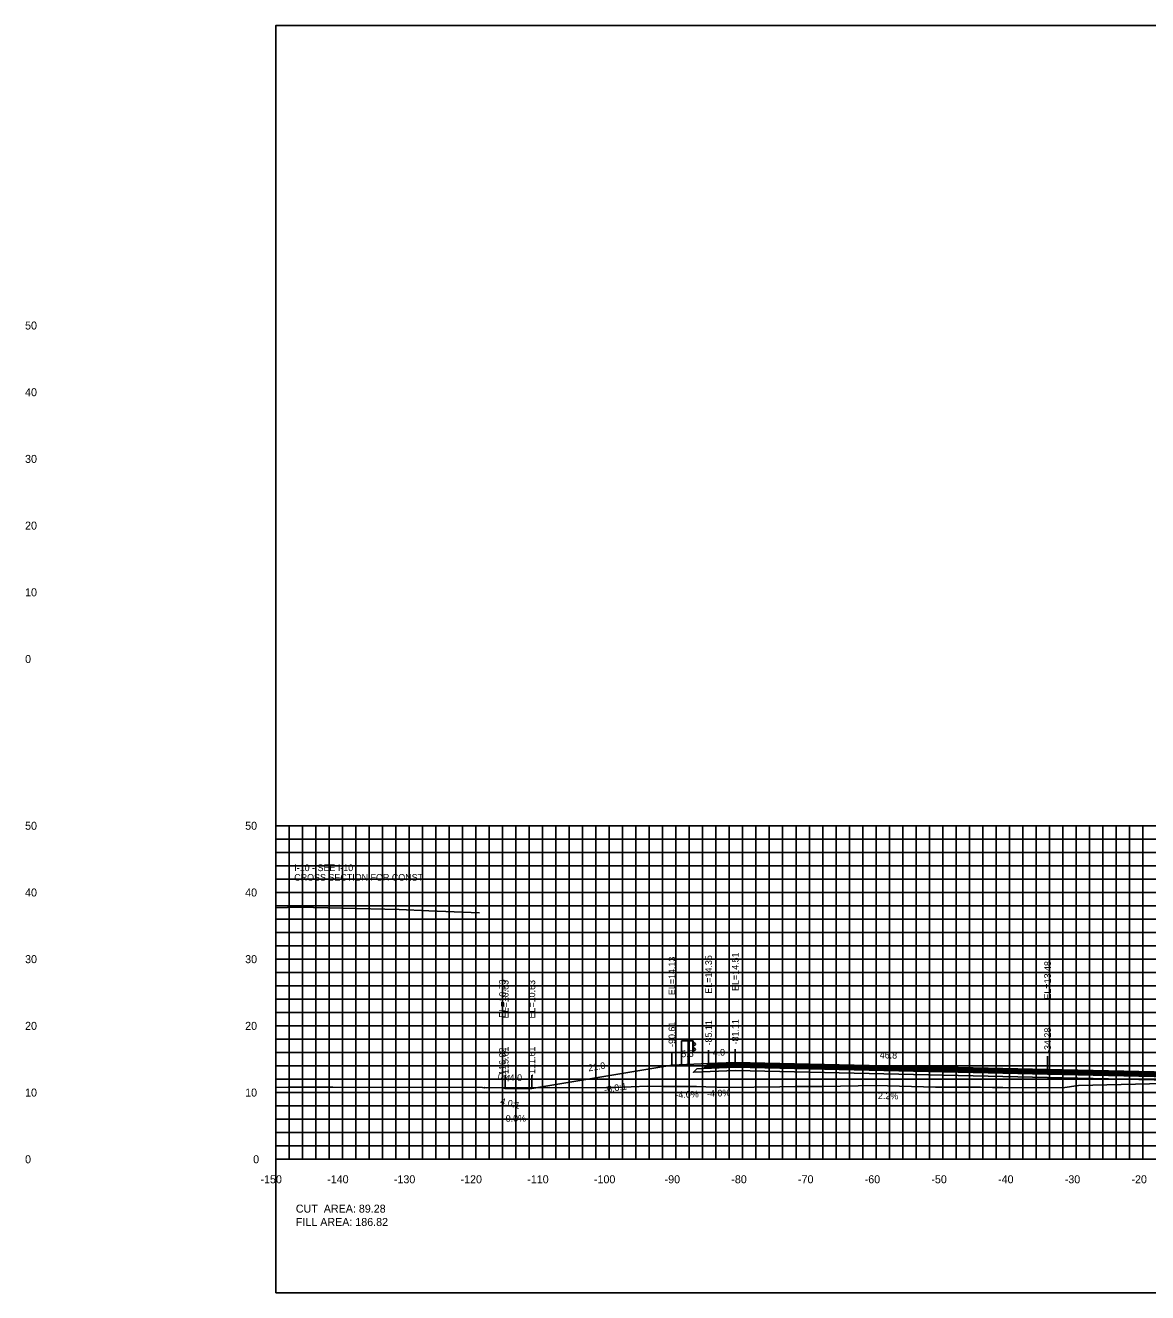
# Model space of a CAD drawing. Extents: x 1800976 to 1805104, y 250057 to 250580.
# Drawn here: x 1804483.4 to 1804651.7, y 250079.4 to 250269.4 of the extents above; entities that cross this region are included whole.
import ezdxf

# ---------------------------------------------------------------- set-up
doc = ezdxf.new("R2010")
doc.units = 0
for name, color, linetype in [('10', 7, 'Continuous'), ('3', 7, 'Continuous'), ('31', 7, 'Continuous'), ('4', 7, 'Continuous'), ('60', 7, 'Continuous'), ('ANNO-TXT', 7, 'Continuous'), ('BASE', 7, 'Continuous'), ('CL-CNST', 7, 'Continuous'), ('Level 1', 7, 'Continuous'), ('Level 62', 7, 'Continuous'), ('LOWER BINDER', 7, 'Continuous'), ('M-ROADS', 7, 'Continuous'), ('UPPER BINDER', 7, 'Continuous'), ('WEARING', 7, 'Continuous')]:
    doc.layers.add(name, color=color, linetype=linetype)

msp = doc.modelspace()

# ---------------------------------------------------------------- linework, layer by layer
for p, q in [((1804580.39, 250113.56), (1804580.39, 250115.56)), ((1804585.89, 250113.78), (1804585.89, 250115.78)), ((1804589.89, 250113.94), (1804589.89, 250115.94)), ((1804636.72, 250112.91), (1804636.72, 250114.91)), ((1804554.98, 250110.17), (1804554.98, 250112.17)), ((1804555.39, 250110.06), (1804555.39, 250112.06)), ((1804559.39, 250110.06), (1804559.39, 250112.06))]:
    msp.add_line(p, q)
msp.add_lwpolyline([(1804521, 250079.43), (1804821, 250079.43), (1804821, 250269.43), (1804521, 250269.43)], close=True)
at = {"layer": '60'}
for p, q in [((1804520.94, 250149.43), (1804521, 250149.43)), ((1804521, 250099.43), (1804521, 250149.43)), ((1804520.94, 250139.43), (1804521, 250139.43)), ((1804520.94, 250129.43), (1804521, 250129.43)), ((1804520.94, 250119.43), (1804521, 250119.43)), ((1804520.94, 250109.43), (1804521, 250109.43)), ((1804520.94, 250099.43), (1804521, 250099.43)), ((1804521, 250099.43), (1804821, 250099.43)), ((1804521, 250099.37), (1804521, 250099.43)), ((1804531, 250099.37), (1804531, 250099.43)), ((1804541, 250099.37), (1804541, 250099.43)), ((1804551, 250099.37), (1804551, 250099.43)), ((1804561, 250099.37), (1804561, 250099.43)), ((1804571, 250099.37), (1804571, 250099.43)), ((1804581, 250099.37), (1804581, 250099.43)), ((1804591, 250099.37), (1804591, 250099.43)), ((1804601, 250099.37), (1804601, 250099.43)), ((1804611, 250099.37), (1804611, 250099.43)), ((1804621, 250099.37), (1804621, 250099.43)), ((1804631, 250099.37), (1804631, 250099.43)), ((1804641, 250099.37), (1804641, 250099.43)), ((1804651, 250099.37), (1804651, 250099.43))]:
    msp.add_line(p, q, dxfattribs=at)
at = {"layer": 'BASE'}
msp.add_lwpolyline([(1804584.14, 250112.99), (1804585.14, 250113.03), (1804589.89, 250113.22), (1804636.73, 250112.2), (1804671, 250111.44), (1804695.43, 250110.91), (1804726.72, 250110.21), (1804735.47, 250109.86), (1804736.47, 250109.82), (1804736.99, 250109.3), (1804726.72, 250109.71), (1804695.43, 250110.41), (1804671, 250110.94), (1804636.73, 250111.7), (1804589.89, 250112.72), (1804583.62, 250112.47)], close=True, dxfattribs=at)
at = {"layer": 'CL-CNST'}
for points in [[(1804521, 250137.15), (1804524.51, 250137.22), (1804530.94, 250137.07), (1804539.49, 250136.87), (1804543.92, 250136.69), (1804551.56, 250136.37)], [(1804554.98, 250110.17), (1804555.39, 250110.06), (1804559.39, 250110.06), (1804580.39, 250113.56), (1804585.89, 250113.78), (1804589.89, 250113.94), (1804636.72, 250112.91), (1804671, 250112.16), (1804695.43, 250111.62), (1804695.43, 250111.62), (1804726.72, 250110.93), (1804734.72, 250110.61), (1804738.01, 250110.48), (1804738.01, 250110.48), (1804744.16, 250108.94)]]:
    msp.add_lwpolyline(points, dxfattribs=at)
at = {"layer": 'Level 1'}
for p, q in [((1804581.81, 250117.18), (1804581.81, 250113.62)), ((1804581.81, 250117.18), (1804583.56, 250117.18)), ((1804582.81, 250117.18), (1804582.81, 250113.66)), ((1804582.86, 250117.18), (1804582.86, 250115.43)), ((1804583.51, 250117.18), (1804583.51, 250115.43)), ((1804583.56, 250117.18), (1804583.56, 250115.43)), ((1804583.56, 250117.03), (1804583.92, 250116.74)), ((1804583.92, 250116.66), (1804583.56, 250116.38)), ((1804583.56, 250116.24), (1804583.92, 250115.94)), ((1804582.81, 250115.43), (1804583.56, 250115.43)), ((1804583.92, 250115.87), (1804583.56, 250115.58))]:
    msp.add_line(p, q, dxfattribs=at)
for centre in [(1804583.89, 250116.7), (1804583.89, 250115.91)]:
    msp.add_arc(centre, 0.05, 313.3792, 45, dxfattribs=at)
at = {"layer": 'Level 62'}
for p, q in [((1804521, 250149.43), (1804821, 250149.43)), ((1804521, 250099.43), (1804521, 250149.43)), ((1804523, 250099.43), (1804523, 250149.43)), ((1804525, 250099.43), (1804525, 250149.43)), ((1804527, 250099.43), (1804527, 250149.43)), ((1804529, 250099.43), (1804529, 250149.43)), ((1804531, 250099.43), (1804531, 250149.43)), ((1804533, 250099.43), (1804533, 250149.43)), ((1804535, 250099.43), (1804535, 250149.43)), ((1804537, 250099.43), (1804537, 250149.43)), ((1804539, 250099.43), (1804539, 250149.43)), ((1804541, 250099.43), (1804541, 250149.43)), ((1804543, 250099.43), (1804543, 250149.43)), ((1804545, 250099.43), (1804545, 250149.43)), ((1804547, 250099.43), (1804547, 250149.43)), ((1804549, 250099.43), (1804549, 250149.43)), ((1804551, 250099.43), (1804551, 250149.43)), ((1804553, 250099.43), (1804553, 250149.43)), ((1804555, 250099.43), (1804555, 250149.43)), ((1804557, 250099.43), (1804557, 250149.43)), ((1804559, 250099.43), (1804559, 250149.43)), ((1804561, 250099.43), (1804561, 250149.43)), ((1804563, 250099.43), (1804563, 250149.43)), ((1804565, 250099.43), (1804565, 250149.43)), ((1804567, 250099.43), (1804567, 250149.43)), ((1804569, 250099.43), (1804569, 250149.43)), ((1804571, 250099.43), (1804571, 250149.43)), ((1804573, 250099.43), (1804573, 250149.43)), ((1804575, 250099.43), (1804575, 250149.43)), ((1804577, 250099.43), (1804577, 250149.43)), ((1804579, 250099.43), (1804579, 250149.43)), ((1804581, 250099.43), (1804581, 250149.43)), ((1804583, 250099.43), (1804583, 250149.43)), ((1804585, 250099.43), (1804585, 250149.43)), ((1804587, 250099.43), (1804587, 250149.43)), ((1804589, 250099.43), (1804589, 250149.43)), ((1804591, 250099.43), (1804591, 250149.43)), ((1804593, 250099.43), (1804593, 250149.43)), ((1804595, 250099.43), (1804595, 250149.43)), ((1804597, 250099.43), (1804597, 250149.43)), ((1804599, 250099.43), (1804599, 250149.43)), ((1804601, 250099.43), (1804601, 250149.43)), ((1804603, 250099.43), (1804603, 250149.43)), ((1804605, 250099.43), (1804605, 250149.43)), ((1804607, 250099.43), (1804607, 250149.43)), ((1804609, 250099.43), (1804609, 250149.43)), ((1804611, 250099.43), (1804611, 250149.43)), ((1804613, 250099.43), (1804613, 250149.43)), ((1804615, 250099.43), (1804615, 250149.43)), ((1804617, 250099.43), (1804617, 250149.43)), ((1804619, 250099.43), (1804619, 250149.43)), ((1804621, 250099.43), (1804621, 250149.43)), ((1804623, 250099.43), (1804623, 250149.43)), ((1804625, 250099.43), (1804625, 250149.43)), ((1804627, 250099.43), (1804627, 250149.43)), ((1804629, 250099.43), (1804629, 250149.43)), ((1804631, 250099.43), (1804631, 250149.43)), ((1804633, 250099.43), (1804633, 250149.43)), ((1804635, 250099.43), (1804635, 250149.43)), ((1804637, 250099.43), (1804637, 250149.43)), ((1804639, 250099.43), (1804639, 250149.43)), ((1804641, 250099.43), (1804641, 250149.43)), ((1804643, 250099.43), (1804643, 250149.43)), ((1804645, 250099.43), (1804645, 250149.43)), ((1804647, 250099.43), (1804647, 250149.43)), ((1804649, 250099.43), (1804649, 250149.43)), ((1804651, 250099.43), (1804651, 250149.43)), ((1804521, 250147.43), (1804821, 250147.43)), ((1804521, 250145.43), (1804821, 250145.43)), ((1804521, 250143.43), (1804821, 250143.43)), ((1804521, 250141.43), (1804821, 250141.43)), ((1804521, 250139.43), (1804821, 250139.43)), ((1804521, 250137.43), (1804821, 250137.43)), ((1804521, 250135.43), (1804821, 250135.43)), ((1804521, 250133.43), (1804821, 250133.43)), ((1804521, 250131.43), (1804821, 250131.43)), ((1804521, 250129.43), (1804821, 250129.43)), ((1804521, 250127.43), (1804821, 250127.43)), ((1804521, 250125.43), (1804821, 250125.43)), ((1804521, 250123.43), (1804821, 250123.43)), ((1804521, 250121.43), (1804821, 250121.43)), ((1804521, 250119.43), (1804821, 250119.43)), ((1804521, 250117.43), (1804821, 250117.43)), ((1804521, 250115.43), (1804821, 250115.43)), ((1804521, 250113.43), (1804821, 250113.43)), ((1804521, 250111.43), (1804821, 250111.43)), ((1804521, 250109.43), (1804821, 250109.43)), ((1804521, 250107.43), (1804821, 250107.43)), ((1804521, 250105.43), (1804821, 250105.43)), ((1804521, 250103.43), (1804821, 250103.43)), ((1804521, 250101.43), (1804821, 250101.43)), ((1804521, 250099.43), (1804821, 250099.43))]:
    msp.add_line(p, q, dxfattribs=at)
at = {"layer": 'LOWER BINDER'}
for points in [[(1804589.89, 250113.41), (1804636.72, 250112.38), (1804671, 250111.63), (1804695.43, 250111.1), (1804726.72, 250110.4), (1804735.27, 250110.06), (1804735.47, 250109.86), (1804726.72, 250110.21), (1804695.43, 250110.91), (1804671, 250111.44), (1804636.73, 250112.2), (1804589.89, 250113.22), (1804585.14, 250113.03), (1804585.34, 250113.23)], [(1804589.89, 250113.6), (1804636.72, 250112.57), (1804671, 250111.82), (1804695.43, 250111.28), (1804726.72, 250110.59), (1804735.08, 250110.26), (1804735.27, 250110.06), (1804726.72, 250110.4), (1804695.43, 250111.1), (1804671, 250111.63), (1804636.72, 250112.38), (1804589.89, 250113.41), (1804585.34, 250113.23), (1804585.53, 250113.43)]]:
    msp.add_lwpolyline(points, close=True, dxfattribs=at)
at = {"layer": 'M-ROADS'}
msp.add_lwpolyline([(1804521, 250110.2), (1804522.83, 250110.26), (1804529.54, 250110.23), (1804551.97, 250110.17), (1804552.01, 250110.17), (1804552.25, 250110.16), (1804552.36, 250110.17), (1804552.64, 250110.16), (1804570.58, 250110.18), (1804571.81, 250110.18), (1804576.72, 250110.37), (1804578.98, 250110.34), (1804580.22, 250110.33), (1804584.1, 250110.34), (1804585.49, 250110.28), (1804588.84, 250110.18), (1804596.57, 250110.31), (1804598.86, 250110.36), (1804600.39, 250110.36), (1804602.82, 250110.36), (1804603.01, 250110.36), (1804603.07, 250110.36), (1804610.9, 250110.51), (1804619.93, 250110.25), (1804621.1, 250110.22), (1804624.72, 250110.26), (1804625.48, 250110.26), (1804626.68, 250110.26), (1804628.45, 250110.19), (1804630.01, 250110.21), (1804638.94, 250110.14), (1804641.38, 250110.51), (1804664.81, 250111.06)], dxfattribs=at)
at = {"layer": 'UPPER BINDER'}
msp.add_lwpolyline([(1804726.72, 250110.59), (1804735.08, 250110.26), (1804734.88, 250110.46), (1804726.72, 250110.78), (1804695.43, 250111.47), (1804671, 250112.01), (1804636.72, 250112.76), (1804589.89, 250113.79), (1804585.73, 250113.63), (1804585.53, 250113.43), (1804589.89, 250113.6), (1804636.72, 250112.57), (1804671, 250111.82), (1804695.43, 250111.28)], close=True, dxfattribs=at)
at = {"layer": 'WEARING'}
msp.add_lwpolyline([(1804726.72, 250110.78), (1804734.88, 250110.46), (1804734.72, 250110.61), (1804726.72, 250110.93), (1804695.43, 250111.62), (1804671, 250112.16), (1804636.72, 250112.91), (1804589.89, 250113.94), (1804585.89, 250113.78), (1804585.73, 250113.63), (1804589.89, 250113.79), (1804636.72, 250112.76), (1804671, 250112.01), (1804695.43, 250111.47)], close=True, dxfattribs=at)

# ---------------------------------------------------------------- texts
for s, rotation, p in [('-6.0:1', 9.4623, (1804570.3, 250109.35)), ('4.0:1', 345.9638, (1804554.58, 250107.69))]:
    msp.add_text(s, height=1, rotation=rotation).set_placement(p)
at = {"layer": '10'}
for s, p in [('-150', (1804518.7, 250095.83)), ('-140', (1804528.7, 250095.83)), ('-130', (1804538.7, 250095.83)), ('-120', (1804548.7, 250095.83)), ('-110', (1804558.7, 250095.83)), ('-100', (1804568.7, 250095.83)), ('-90', (1804579.3, 250095.83)), ('-80', (1804589.3, 250095.83)), ('-70', (1804599.3, 250095.83)), ('-60', (1804609.3, 250095.83)), ('-50', (1804619.3, 250095.83)), ('-40', (1804629.3, 250095.83)), ('-30', (1804639.3, 250095.83)), ('-20', (1804649.3, 250095.83))]:
    msp.add_text(s, height=1.2, dxfattribs=at).set_placement(p)
at = {"layer": '3'}
for s, p in [('I-10 - SEE I-10 ', (1804523.76, 250142.63)), ('CROSS SECTION FOR CONST ', (1804523.76, 250141.19))]:
    msp.add_text(s, height=1, dxfattribs=at).set_placement(p)
for s, p in [('EL=14.13', (1804580.89, 250124.04)), ('EL=14.35', (1804586.39, 250124.26)), ('EL=14.51', (1804590.39, 250124.67)), ('EL=13.48', (1804637.22, 250123.38)), ('EL=10.73', (1804555.48, 250120.64)), ('EL=10.63', (1804555.89, 250120.54)), ('EL=10.63', (1804559.89, 250120.54)), ('-90.61', (1804580.89, 250116.27)), ('-85.11', (1804586.39, 250116.49)), ('-81.11', (1804590.39, 250116.65)), ('-34.28', (1804637.22, 250115.37)), ('-116.02', (1804555.48, 250111.63)), ('-115.61', (1804555.89, 250111.78)), ('-111.61', (1804559.89, 250111.78))]:
    msp.add_text(s, height=1, rotation=90, dxfattribs=at).set_placement(p)
at = {"layer": '31'}
for s, p in [('50', (1804483.4, 250223.83)), ('40', (1804483.4, 250213.83)), ('30', (1804483.4, 250203.83)), ('20', (1804483.4, 250193.83)), ('10', (1804483.4, 250183.83)), ('0', (1804483.4, 250173.83)), ('50', (1804483.4, 250148.83)), ('50', (1804516.4, 250148.83)), ('40', (1804483.4, 250138.83)), ('40', (1804516.4, 250138.83)), ('30', (1804483.4, 250128.83)), ('30', (1804516.4, 250128.83)), ('20', (1804483.4, 250118.83)), ('20', (1804516.4, 250118.83)), ('10', (1804483.4, 250108.83)), ('10', (1804516.4, 250108.83)), ('0', (1804483.4, 250098.83)), ('0', (1804517.6, 250098.83))]:
    msp.add_text(s, height=1.2, dxfattribs=at).set_placement(p)
at = {"layer": '4'}
for s, rotation, p in [('5.5', 2.2906, (1804581.81, 250114.72)), ('4.0', 2.2906, (1804586.52, 250114.91)), ('46.8', 358.7397, (1804611.55, 250114.57)), ('0.4', 345.9638, (1804554.2, 250111.49)), ('21.0', 9.4623, (1804567.91, 250112.6)), ('-4.0%', 2.2906, (1804580.93, 250108.58)), ('-4.0%', 2.2906, (1804585.68, 250108.77)), ('2.2%', 358.7397, (1804611.28, 250108.47))]:
    msp.add_text(s, height=1, rotation=rotation, dxfattribs=at).set_placement(p)
for s, p in [('4.0', (1804556.06, 250111.16)), ('0.0%', (1804555.47, 250105.06))]:
    msp.add_text(s, height=1, dxfattribs=at).set_placement(p)
at = {"layer": '60'}
msp.add_text('-', height=0.0001, dxfattribs=at).set_placement((1804521, 250099.43))
at = {"layer": 'ANNO-TXT'}
for s, p in [('CUT  AREA: 89.28', (1804524, 250091.43)), ('FILL AREA: 186.82', (1804524, 250089.43))]:
    msp.add_text(s, height=1.2, dxfattribs=at).set_placement(p)

doc.saveas('drawing.dxf')
